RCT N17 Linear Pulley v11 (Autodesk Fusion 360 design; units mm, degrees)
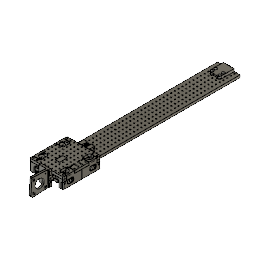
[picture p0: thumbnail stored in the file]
parameter "t_sheet_MAIN" = 6.6 comment "thickness of *most* of the gantry material"
parameter "t_sheet_SECOND" = 6.35 (= "1 / 4 * 1") comment "thickness of the webs"
parameter "od_bearings" = 16
parameter "id_bearings" = 5
parameter "t_bearings" = 5
parameter "p_belt" = 2
parameter "w_belt" = 10
parameter "t_belt" = 1.4
parameter "l_top_belt_to_rail" = 3
parameter "r_cutoutTool" = 2.05 (= "4.1 mm / 2")
parameter "hw_m3_thru" = 3.5
parameter "hw_m3_head" = 5.5
parameter "hw_m3_washer" = 7
parameter "hw_m3_thread" = 2.5
parameter "tab_breather" = 0.2 comment "tab clearance"
parameter "hw_m5_thread" = 4.2
parameter "hw_m5_head" = 8.5
parameter "hw_m5_washer" = 10
parameter "hw_m5_thru" = 5.25
parameter "hw_m6_thru" = 6.5
parameter "hw_m6_head" = 10
parameter "hw_m6_washer" = 12
parameter "l_beltblock" = 15
parameter "hw_plstf6_thread" = 2.94
parameter "hw_plstf6_thru" = 4
parameter "hw_plstf6_head" = 6.86
parameter "hw_plstf6_washer" = 7.92
parameter "hw_m3_flathead" = 6
parameter "hw_m4insert_d" = 6
parameter "hw_m4insert_l" = 4.8
parameter "hw_m4_tappedwj" = 3.3
parameter "hw_m4_thru" = 4.25
parameter "hw_m4_head" = 7
parameter "hw_m4_headheight" = 4
parameter "preload_bearings" = 0.55
parameter "hw_m3insert_d" = 5.4
parameter "hw_m3insert_l" = 3.8
parameter "dist_clearance" = 0.5
parameter "hw_shoulder_headDiameter" = 9
parameter "hw_shoulder_headHeight" = 4
parameter "l_travel" = 400 comment "will be rounded to 10s"
parameter "l_actual_complete" = 490 (= "round(l_travel / 10) * 10 + ( ( nh_gantry_length * 10 ) * 1 mm )")
parameter "nh_rail_width" = "nh_gantry_width - 3"
parameter "l_shoulder_thread" = 10
parameter "hw_n6_thru" = 4.064
parameter "hw_n6_thread" = 3.1
parameter "hw_n6_flathead" = 6.6548
parameter "hw_n6_head" = 6.858
parameter "carriage_offsets" = 0.25
parameter "hw_momentPin_reald" = 3.683
parameter "deg_gt2z" = 23.244 (= "( ( 360 / ( 2 * ( d1013 + d1014 ) / mm * PI / 2 ) ) * 1 deg )")
parameter "d285" = 2
parameter "d344" = 3.5
parameter "d482" = 3.3 (= "t_sheet_MAIN / 2")
parameter "d578" = 0.5
parameter "d689" = 0.5
parameter "d698" = 5
parameter "d701" = 1.7
parameter "d705" = 3.5415 (= "d683 / 2 + 1.7 mm")
parameter "d837" = 0.25
sketch "Basics" plane through (0, 0, 0) normal (0, 1, 0) x axis (1, 0, 0)
  dimension "d560" = 6.6 (= "t_sheet_MAIN")
  dimension "d563" = 5 (= "t_bearings")
  dimension "d564" = 16 (= "od_bearings")
  dimension "d565" = 45 (= "d566")
  dimension "d566" = 45
  dimension "d567" = 10 (= "l_shoulder_thread")
  dimension "d568" = 6.6 (= "t_sheet_MAIN")
  dimension "d569" = 45 (= "( ( nh_gantry_width * 10 ) * 1 mm + 10 mm ) / 2")
  dimension "d571" = 4.5 (= "hw_shoulder_headHeight + 0.5 mm")
  dimension "d572" = 4.5 (= "hw_shoulder_headDiameter / 2")
  dimension "d574" = 8.8037
  dimension "d576" = 0.5
  dimension "d577" = 0.5
  dimension "d580" = 0.5
  dimension "d581" = 3.5 (= "hw_m4insert_d / 2 + 0.5 mm")
  dimension "d582" = 3.5 (= "d581")
  dimension "d583" = 2.1
  dimension "d584" = 0.8383
  dimension "d586" = 1.269 (= "0.5 mm + 0.769 mm")
  dimension "d587" = 5
  dimension "d588" = 10
  dimension "d589" = 5
  dimension "d623" = 0.1
  dimension "d624" = 1.6455
  dimension "d625" = 3.4128
  dimension "d626" = 13.2 (= "0.5 in + 0.5 mm")
  dimension "d696" = 0.5
  dimension "d708" = 0.5
  dimension "d739" = 6
  dimension "d747" = 0.5
  dimension "d748" = 1
  dimension "d801" = 0.275 (= "preload_bearings / 2")
extrude "Extrude48" new body sketch "Basics" along normal blind 50 (= "( nh_gantry_length * 10 + 10 ) / 2 * 1 mm") bodies "Plate"
sketch "Plate Top" plane through (0, 0, 14.3505) normal (0, 0, 1) x axis (-1, 0, 0)
  dimension "d628" = 5
  dimension "d630" = 30
  dimension "d631" = 4.064 (= "hw_n6_thru")
  dimension "d636" = 6.6548 (= "hw_n6_flathead")
  dimension "d637" = 3.1 (= "hw_n6_thread")
  dimension "d638" = 4
  dimension "d639" = 4 (= "d638")
  dimension "d648" = 5
  dimension "d680" = 40
  dimension "d681" = 6
  dimension "d683" = 3.683 (= "hw_momentPin_reald")
  dimension "d691" = 2.54
  dimension "d692" = 0.5 (= "d689")
  dimension "d693" = 0.5
  dimension "d697" = 5
  dimension "d702" = 1.7 (= "d1103")
  dimension "d706" = 2.54 (= "d691")
  dimension "d707" = 3.5
  dimension "d717" = 0.75
  dimension "d718" = 1.7
  dimension "d889" = 3.3 (= "hw_m4_tappedwj")
  dimension "d896" = 0.2
  dimension "d897" = 0.2 (= "d896")
  dimension "d1103" = 1.7
extrude "Extrude57" add sketch "Plate Top" no distance stored
extrude "Extrude51" sketch "Basics" no distance stored from offset 0.25 (= "carriage_offsets")
sketch "Bottom Wheel" plane through (1.1787, 0, -1.1787) normal (0.7071, 0, -0.7071) x axis (0, 1, 0)
  dimension "d601" = 16 (= "od_bearings")
  dimension "d602" = 6 (= "hw_m4insert_d")
  dimension "d603" = 4
  dimension "d604" = 0.25
  dimension "d655" = 1
extrude "Extrude52" cut sketch "Bottom Wheel" against normal blind 20
extrude "Extrude53" new body sketch "Bottom Wheel" blind 5 (= "t_bearings") from offset 0.5 bodies "Bottom Fixed Carriage Wheel"
sketch "Top Wheel" plane through (-2.1213, 0, -2.1213) normal (0.7071, 0, 0.7071) x axis (0, 1, 0)
  dimension "d612" = 0.25
  dimension "d613" = 4
  dimension "d614" = 6 (= "hw_m4insert_d")
  dimension "d615" = 16 (= "od_bearings")
  dimension "d649" = 0.75
extrude "Extrude54" cut sketch "Top Wheel" against normal blind 20
extrude "Extrude55" new body sketch "Top Wheel" blind 5 (= "t_bearings") from offset 0.5 bodies "Top Fixed Carriage Wheel"
extrude "Extrude56" new body sketch "Basics" along normal blind 490 (= "l_actual_complete") bodies "Rail"
extrude "Extrude58" sketch "Basics" to an object
extrude "Extrude59" sketch "Basics" to an object
extrude "Extrude60" sketch "Basics" to an object
combine "Combine6"
fillet "Fillet30" radius 4
extrude "Extrude61" cut sketch "Top Wheel" along normal blind 21
offset_faces "OffsetFaces6"
extrude "Extrude62" sketch "Basics" to an object
extrude "Extrude63" cut sketch "Bottom Wheel" along normal blind 12
combine "Combine5"
fillet "Fillet31" radius 4
fillet "Fillet32" radius 1
fillet "Fillet35" radius 0.5
fillet "Fillet36" radius 0.5
fillet "Fillet37" radius 0.5
fillet "Fillet38" radius 0.5
fillet "Fillet39" radius 0.2
offset_faces "OffsetFaces9" distance 3
fillet "Fillet63" radius 2
fillet "Fillet64" radius 1
extrude "Extrude64" cut sketch "Plate Top" to an object
extrude "Extrude65" sketch "Basics" to an object
extrude "Extrude66" sketch "Basics" to an object offset 5
extrude "Extrude67" cut sketch "Plate Top" to an object
sketch "Top Wheel Floating" plane through (32.1213, 0, -32.1213) normal (-0.7071, 0, 0.7071) x axis (0, -1, 0)
  dimension "d719" = 16 (= "od_bearings")
  dimension "d720" = 6 (= "hw_m4insert_d")
  dimension "d721" = 4
  dimension "d722" = 0.25
  dimension "d725" = 1
  dimension "d789" = 12
  dimension "d790" = 2
  dimension "d791" = 45
extrude "Extrude68" cut sketch "Top Wheel Floating" against normal blind 19
extrude "Extrude69" new body sketch "Top Wheel Floating" blind 5 (= "t_bearings") from offset 0.5 bodies "Top Floating Carriage Wheel"
sketch "Bottom Wheel Floating" plane through (28.8213, 0, 28.8213) normal (-0.7071, 0, -0.7071) x axis (0, -1, 0)
  dimension "d729" = 4
  dimension "d730" = 6 (= "hw_m4insert_d")
  dimension "d731" = 16 (= "od_bearings")
  dimension "d732" = 1
  dimension "d733" = 0.25
extrude "Extrude70" cut sketch "Bottom Wheel Floating" against normal blind 26
extrude "Extrude71" new body sketch "Bottom Wheel Floating" blind 5 (= "t_bearings") from offset 0.5 bodies "Bottom Floating Carriage Wheel"
extrude "Extrude74" sketch "Basics" blind 3
extrude "Extrude75" sketch "Basics" to an object
extrude "Extrude76" new body sketch "Basics" to an object bodies "Floating Carriage Post"
extrude "Extrude77" sketch "Basics" to an object
extrude "Extrude78" cut sketch "Bottom Wheel Floating" along normal blind 12
combine "Combine8"
extrude "Extrude72" sketch "Basics" to an object
fillet "Fillet42" radius 4
offset_faces "OffsetFaces7" distance -1
extrude "Extrude73" cut sketch "Top Wheel Floating" along normal blind 32
combine "Combine7"
extrude "Extrude79" cut sketch "Plate Top" against normal blind 37
extrude "Extrude80" cut sketch "Plate Top" to an object offset 0.5
fillet "Fillet44" radius 3
fillet "Fillet45" radius 2
fillet "Fillet47" radius 3
fillet "Fillet48" radius 3
fillet "Fillet49" radius 1
fillet "Fillet50" radius 0.5
fillet "Fillet51" radius 2
fillet "Fillet55" radius 3
fillet "Fillet57" radius 0.5
sketch "Post Tieback" plane through (75, 0, 0) normal (1, 0, 0) x axis (0, 1, 0)
  dimension "d777" = 5.4 (= "hw_m3insert_d")
  dimension "d778" = 3.5 (= "hw_m3_thru")
extrude "Extrude81" cut sketch "Post Tieback" to an object
extrude "Extrude82" cut sketch "Post Tieback" to an object
fillet "Fillet52" radius 2
fillet "Fillet53" radius 2
fillet "Fillet54" radius 2
offset_faces "OffsetFaces8" distance 3
fillet "Fillet59" radius 2
fillet "Fillet60" radius 2
fillet "Fillet61" radius 1
fillet "Fillet65" radius 2
fillet "Fillet66" radius 4.5
offset_faces "OffsetFaces10" distance -0.5
mirror "Mirror3" bodies "Floating Carriage (1)", "Floating Carriage Post (1)", "Top Floating Carriage Wheel (1)", "Bottom Floating Carriage Wheel (1)", "Fixed Carriage (1)", "Plate (1)", "Top Fixed Carriage Wheel (1)", "Bottom Fixed Carriage Wheel (1)"
combine "Combine9" bodies "Plate (1)"
work_plane "WorkPlane1"
sketch "Pulley" plane through (30, 320, -3.175) normal (1, 0, 0) x axis (0, 1, 0)
  dimension "d898" = 6.6 (= "t_sheet_MAIN")
  dimension "d899" = 490 (= "l_actual_complete")
  dimension "d900" = 100 (= "( nh_gantry_length * 10 + 10 ) * 1 mm")
  dimension "d901" = 10.1859 (= "nt_pinion * p_belt / PI")
  dimension "d903" = 1.38
  dimension "d905" = 1 (= "0.75 mm + 0.25 mm")
  dimension "d907" = 8.1859
  dimension "d908" = 31
  dimension "d909" = 42.3
  dimension "d910" = 3.25
  dimension "d911" = 1.625 (= "( 3.25 / 2 ) * 1 mm")
  dimension "d912" = 3.25
  dimension "d913" = 6.5 (= "2 * d912")
  dimension "d914" = 3.25 (= "d912")
  dimension "d915" = 6.5 (= "d913")
  dimension "d916" = 3.25 (= "d912")
  dimension "d917" = 6.5 (= "d913")
  dimension "d918" = 7.4884
  dimension "d919" = 11.05 (= "( 22.1 / 2 ) * 1 mm")
  dimension "d920" = 2.0045
  dimension "d921" = 0.918
  dimension "d922" = 0.79
  dimension "d924" = 0.1
  dimension "d925" = 0.1
  dimension "d926" = 20
  dimension "d927" = 3.25 (= "d912")
  dimension "d928" = 42.3
  dimension "d929" = 3.25 (= "d912")
  dimension "d932" = 6.9005
  dimension "d937" = 1
  dimension "d938" = 0.1
  dimension "d942" = 0.75
  dimension "d949" = 0.75 (= "d942")
  dimension "d950" = 16 (= "od_bearings")
  dimension "d951" = 5 (= "id_bearings")
  dimension "d952" = 0.1
  dimension "d954" = 20
  dimension "d958" = 20
  dimension "d959" = 0.75
  dimension "d973" = 2.55 (= "( 5.1 / 2 ) * 1 mm")
  dimension "d974" = 15
  dimension "d975" = 7.4 (= "hw_m3insert_d + 2 mm")
  dimension "d976" = 0.25
  dimension "d977" = 0.5
  dimension "d1007" = 50
  dimension "d1008" = 20
  dimension "d1009" = 0.1
  dimension "d1010" = 0.3
  dimension "d1011" = 0.1
  dimension "d1012" = 9.5
  dimension "d1013" = 4
  dimension "d1014" = 0.93 (= "1.38 mm - 0.75 mm + 0.3 mm")
  dimension "d1015" = 3
  dimension "d1016" = 1.35
  dimension "d1017" = 2
  dimension "d1018" = 23.244 (= "deg_gt2z")
  dimension "d1021" = 23.244 (= "deg_gt2z")
  dimension "d1022" = 69.731 (= "deg_gt2z * 3")
  dimension "d1023" = 92.975 (= "deg_gt2z * 4")
  dimension "d1024" = 116.219 (= "deg_gt2z * 5")
  dimension "d1025" = 139.462 (= "deg_gt2z * 6")
  dimension "d1030" = 0.15
  dimension "d1055" = 6
  dimension "d1104" = 0.05
  dimension "d1105" = 5
  dimension "d1106" = 0.7
  dimension "d1107" = 4
  dimension "d1108" = 60
  dimension "d1109" = 0.05
  dimension "d1111" = 0.1
  dimension "d1113" = 2
  dimension "d1114" = 1.35
  dimension "d1115" = 2
  dimension "d1116" = 2
  dimension "d1117" = 2
  dimension "d1118" = 2
  dimension "d1119" = 0.9
  dimension "d1120" = 0.85 (= "( 1.7 / 2 ) * 1 mm")
  dimension "d1122" = 15
  dimension "d1125" = 0.15
  dimension "d1130" = 0.25
  dimension "d1131" = 0.25 (= "d1130")
  dimension "d1139" = 7
extrude "Extrude93" new body sketch "Pulley" blind 5 from offset 5.5
extrude "Extrude94" new body sketch "Pulley" blind 9 from offset 5.5
extrude "Extrude95" sketch "Pulley" blind -11
extrude "Extrude96" sketch "Pulley" blind -9
extrude "Extrude113" sketch "Pulley" blind 9
combine "Combine16"
sketch "Sketch30" plane through (0, -6.1, 0) normal (0, -1, 0) x axis (1, 0, 0)
  dimension "d1059" = 5.4 (= "hw_m3insert_d")
  dimension "d1060" = 4
extrude "Extrude114" cut sketch "Sketch30" to an object
fillet "Fillet93" radius 5
fillet "Fillet94" radius 4
sketch "Sketch31" plane through (0, -6.1, 0) normal (0, -1, 0) x axis (1, 0, 0)
  dimension "d1065" = 5.4 (= "hw_m3insert_d")
  dimension "d1066" = 4.5
  dimension "d1067" = 3.3 (= "t_sheet_MAIN / 2")
extrude "Extrude115" cut sketch "Sketch31" to an object
sketch "Sketch32" plane through (0, 0, 6.7505) normal (0, 0, 1) x axis (-1, 0, 0)
  dimension "d1070" = 5
  dimension "d1071" = 10
  dimension "d1072" = 4.75
  dimension "d1074" = 20
  dimension "d1075" = 20
  dimension "d1078" = 8 (= "hw_m4_head + 1 mm")
extrude "Extrude116" cut sketch "Sketch32" to an object
extrude "Extrude117" cut sketch "Sketch32" against normal blind 4.5 (magnitude of "-4 mm - 0.5 mm")
sketch "Sketch33" plane through (0, -0.1, 0) normal (0, 1, 0) x axis (-1, 0, 0)
  dimension "d1094" = 5.4 (= "hw_m3insert_d")
  dimension "d1095" = 3.5 (= "hw_m3_thru")
extrude "Extrude118" cut sketch "Sketch33" against normal blind 10
extrude "Extrude119" cut sketch "Sketch33" against normal blind 4
fillet "Fillet95" radius 1.5
fillet "Fillet96" radius 4.5
fillet "Fillet97" radius 1
fillet "Fillet98" radius 2
fillet "Fillet99" radius 1
fillet "Fillet100" radius 1
fillet "Fillet101" radius 3
fillet "Fillet102" radius 1
fillet "Fillet103" radius 1
fillet "Fillet104" radius 1
fillet "Fillet105" ChordLen 3
extrude "Extrude97" cut sketch "Pulley" distance 14.75
extrude "Extrude98" new body sketch "Pulley" blind 5 (= "t_bearings") from offset 0.25 bodies "Idler Bearing One"
extrude "Extrude99" new body sketch "Pulley" no distance stored from offset -0.25 bodies "Idlery Bearing Two"
extrude "Extrude100" new body sketch "Pulley" to an object offset -0.25 from offset 5.75 (= "t_bearings + 0.75 mm") bodies "Pulley Idler"
extrude "Extrude101" add sketch "Pulley" to an object
sketch "Sketch27" plane through (0, 414.65, 148.1091) normal (0, -0.9417, -0.3364) x axis (1, 0, 0)
  dimension "d978" = 5.4 (= "hw_m3insert_d")
  dimension "d979" = 3.25
extrude "Extrude102" cut sketch "Sketch27" against normal blind 16
extrude "Extrude103" cut sketch "Sketch27" against normal blind 6
chamfer "Chamfer8" distance 1.075
extrude "Extrude104" sketch "Pulley" blind -2
sketch "Sketch28" plane through (0, 0, 6.7505) normal (0, 0, 1) x axis (-1, 0, 0)
  dimension "d988" = 7.5 (= "hw_m4_head + 0.5 mm")
  dimension "d989" = 5
  dimension "d990" = 10
  dimension "d992" = 4.25 (= "hw_m4_thru")
  dimension "d1102" = 10
extrude "Extrude105" cut sketch "Sketch28" against normal blind 26
combine "Combine12"
extrude "Extrude106" cut sketch "Sketch28" against normal blind 5
fillet "Fillet78" radius 2
fillet "Fillet79" radius 1
fillet "Fillet80" radius 2.5
fillet "Fillet81" radius 8
fillet "Fillet82" radius 1
fillet "Fillet83" radius 5
mirror "Mirror4"
combine "Combine13"
fillet "Fillet84" radius 3
fillet "Fillet85" radius 3.2
fillet "Fillet86" radius 2
extrude "Extrude107" new body sketch "Pulley" distance 5.25
extrude "Extrude108" cut sketch "Pulley" along normal blind 5.5 and against normal blind 6.5
extrude "Extrude109" sketch "Pulley" blind -5
fillet "Fillet87" radius 0.25
fillet "Fillet88" radius 0.5
extrude "Extrude110" sketch "Pulley" blind -1
sketch "Sketch29" plane through (0, 0, 7.6505) normal (0, 0, 1) x axis (-1, 0, 0)
  dimension "d1042" = 4.25 (= "hw_m4_thru")
  dimension "d1100" = 25
extrude "Extrude111" cut sketch "Sketch29" to an object
chamfer "Chamfer9" distance 2.1
mirror "Mirror5"
combine "Combine14"
fillet "Fillet90" radius 5
fillet "Fillet91" radius 0.5
fillet "Fillet92" radius 0.5
extrude "Extrude120" new body sketch "Pulley" distance 11
fillet "Fillet106" ChordLen 0.4
mirror "Mirror6"
combine "Combine17"
extrude "Extrude121" sketch "Pulley" blind -9.5 bodies "Tail Pulley - Y", "Tail Pulley - Block", "Tail Pulley - Underhang"
sketch "Sketch34" plane through (0, 0, 7.6505) normal (0, 0, 1) x axis (-1, 0, 0)
  dimension "d1133" = 5
  dimension "d1134" = 10
  dimension "d1135" = 6 (= "hw_m4insert_d")
extrude "Extrude122" cut sketch "Sketch34" to an object
sketch "Sketch35" plane through (0, 115, 0) normal (0, 1, 0) x axis (-1, 0, 0)
  dimension "d1140" = 6.6548 (= "hw_n6_flathead")
  dimension "d1141" = 3.1 (= "hw_n6_thread")
  dimension "d1142" = 4.064 (= "hw_n6_thru")
  dimension "d1143" = 4.25
extrude "Extrude123" cut sketch "Sketch35" to an object offset 0.7
extrude "Extrude124" cut sketch "Sketch35" to an object
chamfer "Chamfer10" distance 1.4
mirror "Mirror7"
combine "Combine18"
combine "Combine19"
combine "Combine20"
fillet "Fillet107" ChordLen 5
extrude "Extrude45" new body sketch "Plate Top" distance 100
rectangular_pattern "R-Pattern1" countU 10 (= "nh_gantry_length + 1") CountV 9 (= "nh_gantry_width + 1") uSpaceDistance 10 vSpaceDistance -10
combine "Combine11"
sketch "Sketch14" plane through (0, 0, 0) normal (0, 0, 1) x axis (-1, 0, 0)
  dimension "d535" = 3.3 (= "hw_m4_tappedwj")
  dimension "d890" = 5
  dimension "d1101" = 10.275 (= "10 mm + preload_bearings / 2")
extrude "Extrude92" cut sketch "Sketch14" no distance stored
rectangular_pattern "R-Pattern2" uSpaceDistance 10 vSpaceDistance 10
named bodies: "Plate", "Fixed Carriage", "Bottom Fixed Carriage Wheel", "Top Fixed Carriage Wheel", "Rail", "Floating Carriage", "Top Floating Carriage Wheel", "Bottom Floating Carriage Wheel", "Floating Carriage Post", "Floating Carriage (1)", "Floating Carriage Post (1)", "Top Floating Carriage Wheel (1)", "Bottom Floating Carriage Wheel (1)", "Fixed Carriage (1)", "Plate (1)", "Top Fixed Carriage Wheel (1)", "Bottom Fixed Carriage Wheel (1)", "Motor Hanger", "Idler Bearing One", "Idlery Bearing Two", "Pulley Idler", "Tail Pulley - Y", "Tail Pulley - Block", "Tail Pulley - Underhang"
